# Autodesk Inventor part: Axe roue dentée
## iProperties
Created: 2001-06
Part Number: Axe roue dentée
Material: Par défaut
Document SubType Name: Modélisation
Designer: Flavien MARTY
Control State: 0
Master: False
Checked Out: False
Shininess: 21.0
Length Units: 11269
Angle Units: 11279
Time Units: 11290
Mass Units: 11283
Length Display Precision: 3
Angle Display Precision: 2
Compacted: True
Density: 0.0
Volumn: 0.0
Area: 0.0
PropertySet Name: Model Information
Author: Flavien MARTY
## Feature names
1. Extrusion1
2. Chanfrein1 [Chamfer]
